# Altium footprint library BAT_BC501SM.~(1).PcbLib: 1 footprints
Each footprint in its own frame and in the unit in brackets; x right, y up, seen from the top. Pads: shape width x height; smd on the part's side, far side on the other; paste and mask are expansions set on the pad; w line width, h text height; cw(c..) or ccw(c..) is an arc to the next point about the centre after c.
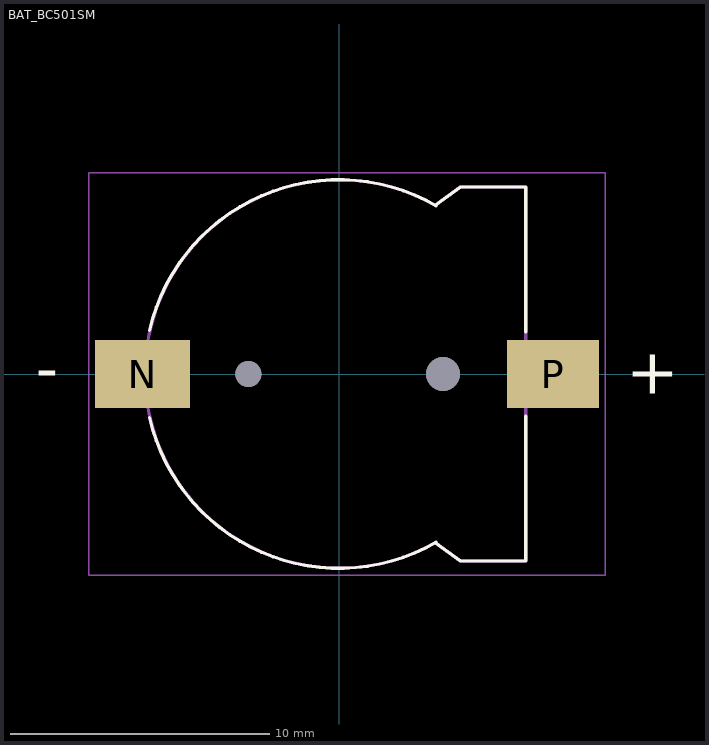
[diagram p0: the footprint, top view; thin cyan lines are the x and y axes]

## BAT_BC501SM [mm]
height 4.25
pads (4):
  rect 3.66x2.6 smd: N(-7.57,0)
  rect 3.54x2.6 smd: P(8.23,0)
  round 1 hole 1 unplated: ""(-3.5,0)
  round 1.3 hole 1.3 unplated: ""(4,0)
Top Overlay:
  lines w0.127: -7.306,-1.681 ccw(c-0.01,0.004) 3.733,-6.481 ; -7.306,1.681 cw(c-0.01,-0.004) 3.733,6.481 ; 3.7,-6.5 4.67,-7.2 7.185,-7.2 7.185,-1.62 ; 3.7,6.5 4.67,7.2 7.185,7.2 7.185,1.62
  text "+" at 11.049,-0.762 h1.78
  text "-" at -11.684,-0.635 h1.78
Mechanical 13:
  lines w0.127: 3.7,-6.5 4.67,-7.2 7.185,-7.2 7.185,7.2 4.67,7.2 3.7,6.5 ; 3.74,-6.477 cw(c0,0) 3.74,6.477
  text "+" at 11.049,-0.762 h1.78
  text "-" at -11.684,-0.635 h1.78
Mechanical 15:
  lines w0.05: -9.65,-7.75 -9.65,7.75 10.25,7.75 10.25,-7.75 -9.65,-7.75
3D body "step_temp.STEP": height 4, standoff -0.94, extent -8.5,-7.491 9.5,7.491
